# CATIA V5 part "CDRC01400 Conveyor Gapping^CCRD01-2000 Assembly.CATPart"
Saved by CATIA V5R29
Part number: CDRC01400 Conveyor Gapping^CCRD01-2000 Assembly
Definition: design
Source: Unknown
Bounding box of the stored display mesh (mm): x -221 to 221, y -14.978 to 14.978, z -15 to 15
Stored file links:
  C:\가치같이\SmartFactory_BoxErectorConveyor\CDRC01400 Conveyor Gapping^CCRD01-2000 Assembly.CATPart
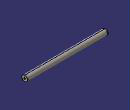
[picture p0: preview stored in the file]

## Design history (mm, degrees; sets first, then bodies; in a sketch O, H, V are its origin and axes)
Body1 "Mirror1" (main body)
  Solid1: solid without history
